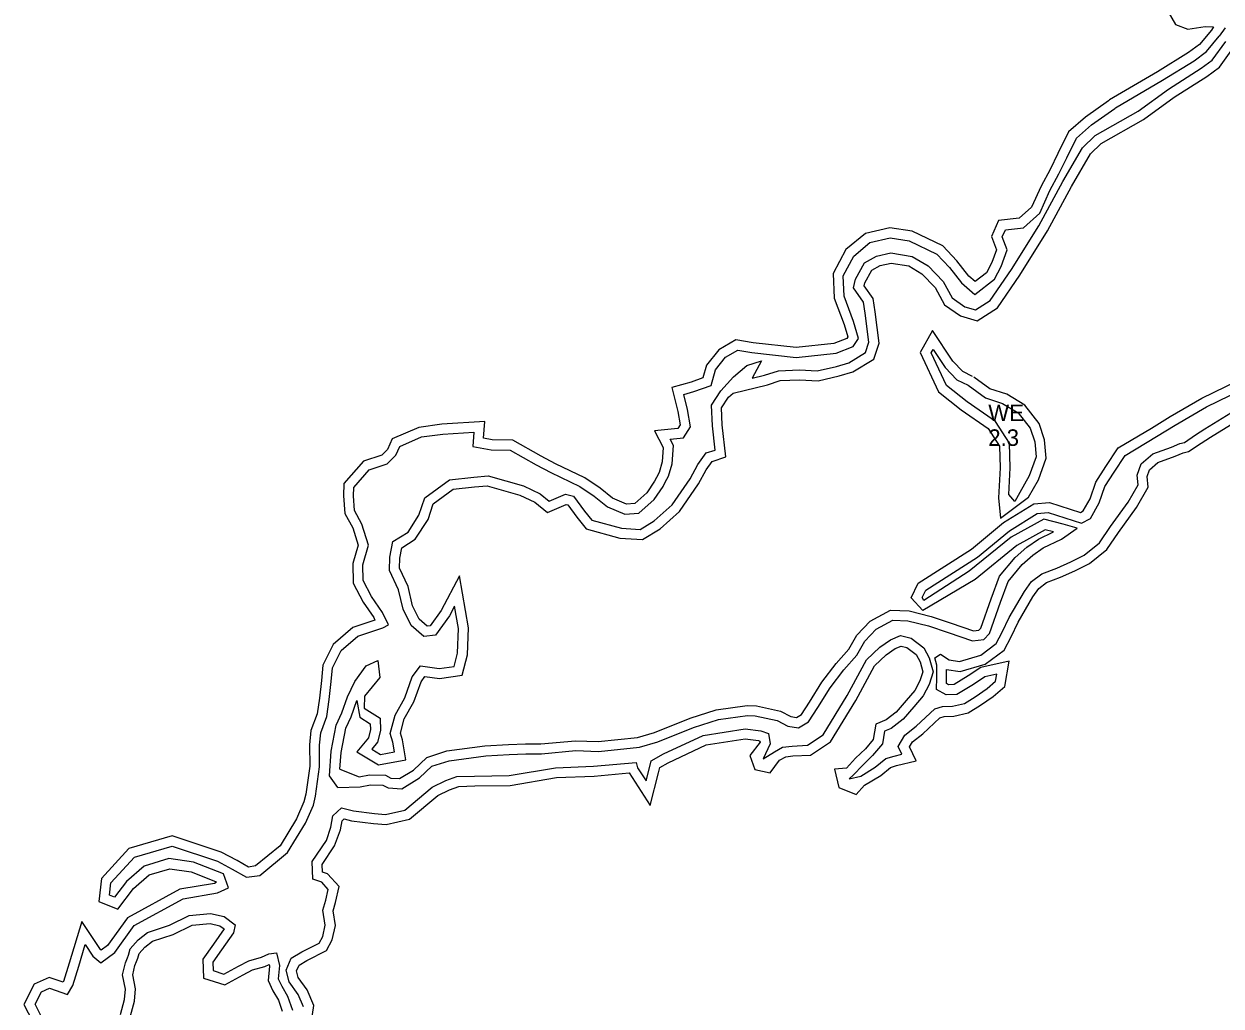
# Model space of a CAD drawing. Extents: x 2160437 to 2172832, y 205694 to 212444.
# Drawn here: x 2165066.3 to 2165428.5, y 210032.9 to 210329.8 of the extents above; entities that cross this region are included whole.
import ezdxf

# ---------------------------------------------------------------- set-up
doc = ezdxf.new("R2010")
doc.units = 0
for name, color, linetype in [('RD_EX_H2O', 7, 'Continuous'), ('RD_EX_H2O_Pond', 7, 'Continuous'), ('RD_EX_H2O_txCode', 7, 'Continuous'), ('RD_EX_VEG_ShrubLine', 7, 'Continuous')]:
    doc.layers.add(name, color=color, linetype=linetype)

msp = doc.modelspace()

# ---------------------------------------------------------------- linework, layer by layer
at = {"layer": 'RD_EX_H2O'}
for points in [[(2165429.66, 210328.63), (2165427.91, 210326.08)], [(2165072.34, 210028.17), (2165069.67, 210033.37), (2165071.61, 210037.18), (2165074.08, 210038.3), (2165079.52, 210036.37), (2165081.06, 210039.04), (2165082.9, 210044.94), (2165084.88, 210051.43), (2165087.17, 210047.96), (2165089.55, 210045.89), (2165093.77, 210049.05), (2165099.65, 210057.17), (2165114.45, 210065.29), (2165124.82, 210067.04), (2165128.16, 210068.62), (2165126.66, 210072.82), (2165117.64, 210076.4), (2165110.19, 210077.43), (2165102.71, 210075.17), (2165097.29, 210070.5), (2165093.7, 210065.8), (2165092.23, 210066.39), (2165092.62, 210070.11), (2165099.72, 210077.87), (2165111.14, 210081.2), (2165124.82, 210076.63), (2165129.32, 210074.22), (2165133.63, 210071.77), (2165137.67, 210072.37), (2165146.08, 210079.31), (2165151.48, 210088.12), (2165153.86, 210093.6), (2165154.52, 210096.3), (2165155.75, 210105.17), (2165155.71, 210111.71), (2165156.08, 210115.51), (2165157.96, 210120.43), (2165158.68, 210125.56), (2165159.29, 210130.98), (2165159.68, 210135.12), (2165162.29, 210140.32), (2165167.34, 210144.67), (2165174.87, 210147.21), (2165176.57, 210148.07), (2165174.75, 210151.81), (2165171.46, 210156.69), (2165168.94, 210161.52), (2165168.84, 210166.3), (2165170.57, 210172.24), (2165168.54, 210178.6), (2165166.34, 210182.69), (2165165.98, 210187.16), (2165166.06, 210189.65), (2165170.72, 210195.01), (2165176.2, 210196.83), (2165178.83, 210199.38), (2165180.01, 210202.04), (2165186.62, 210204.92), (2165193.01, 210205.8), (2165202.42, 210206.36), (2165202.08, 210202.08), (2165207.62, 210201.06), (2165213.39, 210200.96), (2165221.3, 210196.49), (2165225.72, 210194.17), (2165234.45, 210189.94), (2165238.81, 210187.05), (2165242.83, 210183.83), (2165248.06, 210181.57), (2165252.32, 210181.84), (2165257, 210186.05), (2165259.64, 210189.98), (2165260.32, 210191.24), (2165261.26, 210193.09), (2165262.39, 210196.85), (2165262.77, 210202.31), (2165261.78, 210204.25), (2165265.85, 210204.66), (2165267.98, 210207.97), (2165267.02, 210213.25), (2165265.93, 210217.81), (2165269.01, 210218.67), (2165274.19, 210220.5), (2165275.52, 210225.25), (2165278.51, 210229.01), (2165282.23, 210231.2), (2165286.51, 210230.44), (2165299.93, 210228.93), (2165312.01, 210230.22), (2165317.21, 210232.23), (2165318.79, 210234.7), (2165317.3, 210239.86), (2165314.4, 210247.5), (2165314.13, 210253.67), (2165317.32, 210259.63), (2165322.23, 210263.68), (2165328.39, 210265.15), (2165334.12, 210264.28), (2165342.45, 210260.23), (2165346.29, 210256.19), (2165349.97, 210251.5), (2165353.96, 210248.05), (2165359.88, 210252.62), (2165361.9, 210256.52), (2165363.71, 210261.53), (2165362.25, 210265.41), (2165363.21, 210267.56), (2165368.7, 210268.19), (2165373.64, 210272.58), (2165376.69, 210279.45), (2165379.4, 210284.48), (2165381.75, 210289.37), (2165384.68, 210295.32), (2165389.31, 210299.26), (2165396.31, 210304.24), (2165396.52, 210304.45), (2165410.78, 210312.81), (2165420.34, 210318.7), (2165424.02, 210321.44), (2165427.91, 210326.08)], [(2165161.3, 210098.98), (2165158.71, 210102.47), (2165159.28, 210109.95), (2165160.78, 210117.79), (2165162.52, 210121.46), (2165164.21, 210126.34), (2165166.44, 210130.98), (2165169.83, 210135.77), (2165173.41, 210137.36), (2165173.99, 210132.19), (2165169.35, 210126.58), (2165169.27, 210122.9), (2165174.05, 210119.88), (2165174.15, 210116.18), (2165173.28, 210112.61), (2165171.56, 210110.5), (2165174.16, 210108.92), (2165178.39, 210109.68), (2165177.91, 210112.65), (2165177.06, 210115.31), (2165178.59, 210120.8), (2165181.51, 210126.04), (2165183.77, 210132.35), (2165186.27, 210135.68), (2165191.97, 210134.89), (2165196.45, 210135.53), (2165197.49, 210139.51), (2165197.78, 210147.05), (2165196.61, 210153.74), (2165195.08, 210150.82), (2165190.81, 210144.99), (2165187.3, 210144.63), (2165183.44, 210147.96), (2165181.01, 210152.87), (2165179.66, 210158.75), (2165176.91, 210164.58), (2165177.02, 210168.6), (2165177.9, 210173.31), (2165182.53, 210176.17), (2165185.82, 210181.3), (2165187.54, 210186.53), (2165195.06, 210192), (2165202.36, 210192.78), (2165206.71, 210193.13), (2165217.39, 210190.19), (2165222.48, 210187.75), (2165225.16, 210185.55), (2165230.1, 210187.62), (2165232.6, 210187.05), (2165235.9, 210182.47), (2165238.11, 210179.75), (2165247.05, 210177.34), (2165252.71, 210176.99), (2165256.96, 210179.54), (2165262.4, 210184.38), (2165267.82, 210192.28), (2165270.15, 210196.58), (2165272.66, 210200.08), (2165275.39, 210200.97), (2165274.58, 210208.34), (2165274.34, 210214.56), (2165277.09, 210218.85), (2165280.99, 210223.06), (2165284.98, 210226.5), (2165289.4, 210227.96), (2165286.63, 210222.66), (2165290.39, 210223.57), (2165294.54, 210224.96), (2165300.95, 210225.23), (2165306.31, 210224.89), (2165312.14, 210226.26), (2165315.81, 210227.39), (2165320.87, 210230.42), (2165321.93, 210233.61), (2165320.84, 210242.36), (2165320.31, 210245.65), (2165317.29, 210250.05), (2165317.91, 210252.65), (2165320.64, 210257.61), (2165324.21, 210259.57), (2165328.55, 210260.58), (2165335.03, 210259.5), (2165339.82, 210256.66), (2165344.38, 210251.94), (2165347.09, 210246.96), (2165350.99, 210244.27), (2165354.22, 210243.32), (2165358.65, 210246.15), (2165365.09, 210255.52), (2165373.35, 210268.76), (2165380.6, 210282.14), (2165386.53, 210292.4), (2165390.41, 210296.13), (2165403.41, 210303.43), (2165412.54, 210310.11), (2165422.41, 210316.4), (2165425.8, 210318.91), (2165429.89, 210324.54)], [(2165161.3, 210098.98), (2165168.04, 210099.17), (2165171.13, 210099.78), (2165174.91, 210099.66), (2165176.52, 210098.83), (2165180.65, 210098.55), (2165185.99, 210101.82), (2165189.73, 210105.38), (2165194.9, 210107.04), (2165205.99, 210108.53), (2165213.06, 210108.93), (2165218.11, 210109.09), (2165222.84, 210109.09), (2165233.29, 210110.09), (2165240.12, 210109.82), (2165252.5, 210111.1), (2165258.06, 210112.71), (2165268.85, 210117.03), (2165276.41, 210119.49), (2165285.21, 210120.68), (2165287.52, 210120.62), (2165294.14, 210119.18), (2165297.4, 210117.5), (2165300.66, 210117.01), (2165303.67, 210118.79), (2165306.49, 210123.12), (2165310.21, 210129.08), (2165314.3, 210134.51), (2165318.31, 210138.97), (2165320.74, 210143.23), (2165324.13, 210146.81), (2165329.16, 210149.5), (2165333.65, 210149.36), (2165339.95, 210147.77), (2165345.86, 210145.81), (2165353.29, 210143.24), (2165356.65, 210143.66), (2165358.43, 210145.51), (2165361.74, 210155.01), (2165364.1, 210161.27), (2165368.33, 210166.35), (2165371.51, 210169.19), (2165374.69, 210171.38), (2165380.19, 210174.03), (2165384.91, 210177.39), (2165380.74, 210178.52), (2165374.88, 210180.04), (2165365, 210174.66), (2165352.26, 210164.3), (2165338.57, 210155.46), (2165338.08, 210156.39), (2165339.13, 210158.62), (2165354.74, 210168.54), (2165364.42, 210176.59), (2165372.79, 210181.81), (2165376.19, 210182.04), (2165386.24, 210178.9), (2165388.95, 210180.28), (2165391.6, 210185.03), (2165393.29, 210189.92), (2165396.08, 210194.32), (2165399.45, 210199.35), (2165408.97, 210205.02), (2165414.6, 210208.52), (2165424.06, 210214.03), (2165438.35, 210221)], [(2165150.89, 210032.59), (2165149.31, 210036.31), (2165146.54, 210040.21), (2165145.62, 210043.67), (2165147.14, 210047.31), (2165150.41, 210049.28), (2165155.64, 210051.88), (2165156.68, 210053.9), (2165157.48, 210057.32), (2165156.77, 210061.86), (2165157.62, 210064.87), (2165158.35, 210068.14), (2165156.39, 210070.27), (2165153.68, 210071.26), (2165153.49, 210076.56), (2165157.82, 210082.94), (2165159.19, 210086.92), (2165159.75, 210090.41), (2165162.38, 210092.75), (2165165.96, 210091.85), (2165172.4, 210091.03), (2165175.7, 210090.77), (2165181.56, 210092.1), (2165189.84, 210099), (2165193.9, 210101.01), (2165197.3, 210102.25), (2165202.61, 210102.39), (2165213.11, 210102.56), (2165227.1, 210104.92), (2165238.6, 210105.37), (2165251.48, 210106.52), (2165251.95, 210104.93), (2165254.56, 210100.9), (2165255.39, 210104.12), (2165256.05, 210106.95), (2165259.82, 210109.11), (2165271.8, 210114.7), (2165284.47, 210116.64), (2165289.18, 210116.05), (2165291.59, 210115.28), (2165292.1, 210112.15), (2165289.95, 210107.65), (2165293.33, 210109.74), (2165295.82, 210111.09), (2165298.66, 210111.48), (2165303.31, 210111.7), (2165308.12, 210114.9), (2165315.33, 210126.77), (2165321.23, 210137.52), (2165325.23, 210141.38), (2165328.41, 210143.57), (2165331.44, 210144.86), (2165334.68, 210144.05), (2165338.53, 210141.12), (2165340.2, 210138.13), (2165341.37, 210133.86), (2165340.13, 210130.07), (2165338.33, 210126.61), (2165335.47, 210123.33), (2165332.27, 210119.56), (2165328.64, 210116.79), (2165326.69, 210115.98), (2165326.05, 210112.16), (2165323.04, 210108.61), (2165320.05, 210105.72), (2165317.18, 210102.64), (2165315.94, 210101.6), (2165319.48, 210102.4), (2165323.83, 210105.06), (2165327.03, 210107.68), (2165329.52, 210108.44), (2165331.87, 210109.01), (2165330.76, 210111.3), (2165332.8, 210114.8), (2165336.25, 210117.47), (2165341.83, 210122.67), (2165344.14, 210123.44), (2165347.18, 210123.53), (2165350.82, 210124.37), (2165354.05, 210126.32), (2165357.73, 210128.86), (2165360.25, 210131.04), (2165360.62, 210133.21), (2165357.02, 210132.41), (2165353.55, 210130.11), (2165348.55, 210127.08), (2165345.3, 210127), (2165342.42, 210128.54), (2165342.44, 210132.22), (2165342.44, 210135.94), (2165341.9, 210138.18), (2165343.54, 210139.23), (2165346.22, 210137.5), (2165349.31, 210137.05), (2165355.74, 210138.91), (2165360.47, 210142.48), (2165362.24, 210145.86), (2165364.37, 210150.33), (2165368.97, 210158.21), (2165371.14, 210161.27), (2165374.21, 210163.53), (2165378.73, 210165.27), (2165382.97, 210167.14), (2165387, 210169.19), (2165391.64, 210172.91), (2165394.98, 210177.81), (2165400.39, 210185.21), (2165403.34, 210190.43), (2165403.05, 210193.35), (2165404.26, 210196.77), (2165407.77, 210199.82), (2165413.44, 210201.86), (2165416, 210202.98), (2165417.38, 210203.3), (2165420.74, 210205.55), (2165423.57, 210207.41), (2165434, 210213.82)], [(2165095.55, 210030.31), (2165096.74, 210034.81), (2165097.01, 210037.93), (2165096.16, 210042.29), (2165097.01, 210045.96), (2165097.59, 210047.47), (2165097.93, 210048.25), (2165098.41, 210050.2), (2165100.82, 210052.87), (2165103.73, 210055.11), (2165110.36, 210057.27), (2165116.34, 210060.22), (2165122.79, 210060.84), (2165126.85, 210059.94), (2165130.18, 210057.38), (2165129.71, 210054.98), (2165126.08, 210049.88), (2165123.44, 210046.1), (2165123.54, 210043.55), (2165126.77, 210042.53), (2165131.19, 210044.92), (2165134.37, 210046.56), (2165138.17, 210047.63), (2165140.35, 210048.62), (2165142.73, 210048.91), (2165143.65, 210045.11), (2165143.22, 210041.11), (2165144.31, 210038.89), (2165146.04, 210035.84), (2165147.51, 210031.6)]]:
    msp.add_lwpolyline(points, dxfattribs=at)
at = {"layer": 'RD_EX_H2O_Pond'}
msp.add_lwpolyline([(2165351.91, 210220.56), (2165357.16, 210216.74), (2165362.37, 210215.09), (2165367.11, 210212.27), (2165370.71, 210207.55), (2165372.08, 210203.47), (2165372.51, 210198.91), (2165370.44, 210193.17), (2165367.63, 210188.18), (2165366.1, 210185.39), (2165364.23, 210187.53), (2165364.67, 210195.55), (2165364.42, 210203.09), (2165360.22, 210209.57), (2165351.6, 210215.55), (2165345.39, 210220.46), (2165340.79, 210230.35), (2165341.36, 210231.36), (2165344.99, 210225.91), (2165348.57, 210222.23)], close=True, dxfattribs=at)
at = {"layer": 'RD_EX_VEG_ShrubLine'}
for points in [[(2165411.32, 210335.42), (2165414.65, 210329.69), (2165418.36, 210328.2), (2165418.36, 210328.2), (2165423.68, 210329.01), (2165426.2, 210328.89), (2165425.52, 210327.9), (2165421.94, 210323.64), (2165418.65, 210321.18), (2165409.23, 210315.38), (2165394.69, 210306.85), (2165394.38, 210306.55), (2165387.46, 210301.63), (2165382.27, 210297.2), (2165379.05, 210290.68), (2165376.72, 210285.84), (2165373.99, 210280.77), (2165371.16, 210274.4), (2165367.41, 210271.06), (2165361.16, 210270.35), (2165359.01, 210265.51), (2165360.51, 210261.51), (2165359.15, 210257.72), (2165357.52, 210254.59), (2165354.06, 210251.93), (2165352.15, 210253.58), (2165348.57, 210258.15), (2165344.25, 210262.69), (2165335.02, 210267.18), (2165328.27, 210268.2), (2165320.86, 210266.44), (2165314.95, 210261.57), (2165311.1, 210254.36), (2165311.42, 210246.89), (2165314.45, 210238.91), (2165315.53, 210235.17), (2165315.21, 210234.67), (2165311.29, 210233.16), (2165299.93, 210231.94), (2165286.94, 210233.41), (2165281.67, 210234.34), (2165276.51, 210231.32), (2165272.79, 210226.64), (2165271.73, 210222.81), (2165268.11, 210221.53), (2165262.34, 210219.93), (2165264.09, 210212.63), (2165264.82, 210208.6), (2165264.11, 210207.5), (2165257.09, 210206.8), (2165259.72, 210201.69), (2165259.42, 210197.39), (2165258.47, 210194.21), (2165257.66, 210192.63), (2165257.07, 210191.53), (2165254.72, 210188.04), (2165251.09, 210184.77), (2165248.59, 210184.61), (2165244.39, 210186.42), (2165240.58, 210189.48), (2165235.94, 210192.55), (2165227.07, 210196.85), (2165222.73, 210199.13), (2165214.2, 210203.95), (2165207.92, 210204.05), (2165205.29, 210204.54), (2165205.69, 210209.56), (2165192.71, 210208.79), (2165185.8, 210207.83), (2165177.74, 210204.32), (2165176.33, 210201.13), (2165174.61, 210199.47), (2165168.99, 210197.6), (2165163.1, 210190.81), (2165162.98, 210187.09), (2165163.4, 210181.83), (2165165.76, 210177.42), (2165167.44, 210172.2), (2165165.83, 210166.7), (2165165.95, 210160.76), (2165168.98, 210155.01), (2165168.98, 210155.01), (2165172.15, 210150.31), (2165172.51, 210149.57), (2165165.82, 210147.33), (2165159.87, 210142.2), (2165156.75, 210135.97), (2165156.3, 210131.29), (2165155.7, 210125.93), (2165155.04, 210121.18), (2165153.13, 210116.2), (2165152.71, 210111.85), (2165152.75, 210105.36), (2165151.56, 210096.87), (2165151, 210094.56), (2165148.81, 210089.5), (2165143.78, 210081.3), (2165136.4, 210075.21), (2165134.21, 210074.89), (2165130.77, 210076.84), (2165126.01, 210079.4), (2165111.2, 210084.34), (2165098.07, 210080.52), (2165089.74, 210071.41), (2165089.01, 210064.46), (2165094.7, 210062.16), (2165099.48, 210068.43), (2165104.19, 210072.48), (2165110.43, 210074.36), (2165116.87, 210073.48), (2165124.29, 210070.53), (2165124.42, 210070.17), (2165123.91, 210069.93), (2165113.45, 210068.16), (2165097.61, 210059.48), (2165091.6, 210051.18), (2165089.69, 210049.74), (2165089.45, 210049.95), (2165083.87, 210058.41), (2165080.03, 210045.82), (2165078.29, 210040.25), (2165078.17, 210040.03), (2165073.94, 210041.53), (2165069.41, 210039.48), (2165066.31, 210033.36), (2165070.19, 210025.79)], [(2165161.87, 210104.45), (2165162.25, 210109.55), (2165163.65, 210116.85), (2165165.3, 210120.32), (2165166.98, 210125.2), (2165167.95, 210120.19), (2165171.09, 210118.2), (2165171.14, 210116.5), (2165170.52, 210113.98), (2165167.06, 210109.71), (2165173.58, 210105.77), (2165181.83, 210107.25), (2165180.84, 210113.36), (2165180.19, 210115.37), (2165181.38, 210119.65), (2165184.25, 210124.79), (2165186.44, 210130.91), (2165187.61, 210132.46), (2165191.98, 210131.86), (2165198.85, 210132.85), (2165200.48, 210139.06), (2165200.79, 210147.25), (2165198.06, 210162.93), (2165192.53, 210152.42), (2165189.18, 210147.84), (2165188.28, 210147.74), (2165185.86, 210149.83), (2165183.85, 210153.89), (2165182.51, 210159.73), (2165179.93, 210165.21), (2165180.01, 210168.28), (2165180.61, 210171.45), (2165184.69, 210173.98), (2165188.55, 210180), (2165190.09, 210184.67), (2165196.18, 210189.11), (2165202.64, 210189.8), (2165206.42, 210190.1), (2165216.34, 210187.37), (2165220.86, 210185.21), (2165224.65, 210182.08), (2165230.37, 210184.48), (2165230.83, 210184.37), (2165233.52, 210180.64), (2165236.4, 210177.1), (2165246.56, 210174.36), (2165253.45, 210173.94), (2165258.74, 210177.11), (2165264.67, 210182.38), (2165270.38, 210190.71), (2165272.7, 210194.99), (2165274.52, 210197.53), (2165278.64, 210198.87), (2165277.58, 210208.56), (2165277.38, 210213.74), (2165279.47, 210217.01), (2165280.91, 210218.19), (2165291.22, 210220.68), (2165295.09, 210221.98), (2165300.92, 210222.23), (2165306.57, 210221.87), (2165312.92, 210223.37), (2165317.04, 210224.63), (2165323.37, 210228.42), (2165324.99, 210233.31), (2165323.81, 210242.78), (2165323.17, 210246.79), (2165320.52, 210250.65), (2165320.73, 210251.56), (2165322.85, 210255.4), (2165325.29, 210256.74), (2165328.65, 210257.52), (2165333.98, 210256.64), (2165337.94, 210254.28), (2165341.94, 210250.15), (2165344.79, 210244.9), (2165349.68, 210241.53), (2165354.68, 210240.06), (2165360.78, 210243.95), (2165367.6, 210253.88), (2165375.94, 210267.25), (2165383.22, 210280.68), (2165388.92, 210290.53), (2165392.21, 210293.71), (2165405.04, 210300.9), (2165414.24, 210307.63), (2165424.11, 210313.93), (2165427.95, 210316.78), (2165432.53, 210323.12)], [(2165353.25, 210223.25), (2165350.37, 210224.68), (2165347.33, 210227.8), (2165341.14, 210237.09), (2165337.42, 210230.48), (2165342.97, 210218.55), (2165349.82, 210213.14), (2165358.02, 210207.44), (2165361.45, 210202.16), (2165361.67, 210195.58), (2165361.17, 210186.48), (2165361.72, 210180.39), (2165370.25, 210186.72), (2165373.18, 210191.92), (2165375.56, 210198.52), (2165375.03, 210204.1), (2165373.4, 210208.98), (2165369.14, 210214.55), (2165363.6, 210217.84), (2165358.54, 210219.45), (2165353.68, 210222.99)], [(2165161.87, 210104.45), (2165167.71, 210102.16), (2165170.88, 210102.79), (2165175.68, 210102.64), (2165177.34, 210101.78), (2165179.9, 210101.61), (2165184.16, 210104.21), (2165188.16, 210108.02), (2165194.23, 210109.98), (2165205.71, 210111.52), (2165212.93, 210111.93), (2165218.06, 210112.09), (2165222.7, 210112.09), (2165233.21, 210113.09), (2165240.02, 210112.82), (2165251.92, 210114.06), (2165257.09, 210115.55), (2165267.83, 210119.85), (2165275.74, 210122.43), (2165285.05, 210123.69), (2165287.89, 210123.61), (2165295.16, 210122.03), (2165298.34, 210120.39), (2165300.05, 210120.13), (2165301.54, 210121.01), (2165303.96, 210124.73), (2165307.73, 210130.77), (2165311.98, 210136.42), (2165315.87, 210140.73), (2165318.31, 210145.02), (2165322.28, 210149.23), (2165328.45, 210152.52), (2165334.07, 210152.35), (2165340.8, 210150.65), (2165346.82, 210148.65), (2165353.61, 210146.3), (2165355.22, 210146.5), (2165355.81, 210147.12), (2165358.92, 210156.03), (2165361.47, 210162.8), (2165366.17, 210168.44), (2165369.65, 210171.56), (2165373.19, 210173.98), (2165377.77, 210176.2), (2165375.28, 210176.84), (2165366.68, 210172.15), (2165354.03, 210161.87), (2165338.21, 210152.49), (2165334.74, 210156.32), (2165336.79, 210160.69), (2165352.97, 210170.97), (2165362.66, 210179.03), (2165371.84, 210184.75), (2165376.55, 210185.07), (2165385.97, 210182.13), (2165386.77, 210182.54), (2165388.85, 210186.26), (2165390.56, 210191.23), (2165393.56, 210195.96), (2165397.33, 210201.59), (2165407.41, 210207.58), (2165413.05, 210211.09), (2165422.64, 210216.68), (2165437.16, 210223.75)], [(2165152.72, 210024.17), (2165153.98, 210032.99), (2165151.94, 210037.79), (2165149.3, 210041.5), (2165148.78, 210043.46), (2165149.53, 210045.25), (2165151.85, 210046.65), (2165157.85, 210049.63), (2165159.52, 210052.85), (2165160.54, 210057.21), (2165159.83, 210061.68), (2165160.53, 210064.13), (2165161.63, 210069.02), (2165158.1, 210072.83), (2165156.61, 210073.38), (2165156.52, 210075.69), (2165160.3, 210081.26), (2165160.3, 210081.26), (2165162.11, 210086.18), (2165162.54, 210088.88), (2165163.19, 210089.46), (2165165.41, 210088.9), (2165172.09, 210088.05), (2165175.92, 210087.74), (2165182.93, 210089.33), (2165191.49, 210096.47), (2165195.09, 210098.25), (2165197.87, 210099.27), (2165202.67, 210099.39), (2165213.39, 210099.56), (2165227.41, 210101.93), (2165238.79, 210102.37), (2165249.42, 210103.32), (2165255.76, 210093.53), (2165258.31, 210103.41), (2165258.68, 210105), (2165261.21, 210106.44), (2165272.68, 210111.8), (2165284.51, 210113.61), (2165288.53, 210113.11), (2165288.92, 210112.98), (2165288.98, 210112.6), (2165285.93, 210108.56), (2165287.41, 210104.42), (2165292.07, 210103.35), (2165294.84, 210107.15), (2165296.77, 210108.2), (2165298.94, 210108.49), (2165304.28, 210108.74), (2165310.34, 210112.77), (2165317.93, 210125.27), (2165323.65, 210135.68), (2165327.13, 210139.05), (2165329.86, 210140.92), (2165331.69, 210141.71), (2165333.35, 210141.29), (2165336.22, 210139.11), (2165337.41, 210136.98), (2165338.24, 210133.94), (2165337.36, 210131.23), (2165335.84, 210128.31), (2165333.19, 210125.28), (2165330.19, 210121.75), (2165327.13, 210119.41), (2165324.01, 210118.11), (2165323.23, 210113.47), (2165320.85, 210110.67), (2165317.9, 210107.82), (2165315.12, 210104.82), (2165311.49, 210104.52), (2165312.83, 210098.95), (2165318.02, 210096.81), (2165320.62, 210099.59), (2165325.57, 210102.6), (2165328.47, 210104.98), (2165330.31, 210105.54), (2165336.19, 210106.98), (2165334.16, 210111.18), (2165335.09, 210112.79), (2165338.2, 210115.18), (2165343.39, 210120.02), (2165344.67, 210120.45), (2165347.57, 210120.54), (2165351.96, 210121.55), (2165355.68, 210123.8), (2165359.56, 210126.48), (2165363.03, 210129.47), (2165364.31, 210137.11), (2165355.83, 210135.21), (2165351.94, 210132.65), (2165347.67, 210130.06), (2165346.02, 210130.02), (2165345.43, 210130.33), (2165345.44, 210132.22), (2165345.44, 210134.58), (2165349.53, 210133.99), (2165357.1, 210136.18), (2165362.81, 210140.49), (2165364.92, 210144.51), (2165367.03, 210148.93), (2165371.5, 210156.58), (2165373.31, 210159.14), (2165375.67, 210160.88), (2165379.87, 210162.5), (2165384.26, 210164.42), (2165388.63, 210166.65), (2165393.87, 210170.85), (2165397.44, 210176.08), (2165402.92, 210183.58), (2165406.42, 210189.79), (2165406.1, 210192.98), (2165406.83, 210195.02), (2165409.32, 210197.19), (2165414.55, 210199.07), (2165416.95, 210200.12), (2165418.59, 210200.5), (2165422.4, 210203.05), (2165425.22, 210204.9), (2165425.22, 210204.9), (2165435.24, 210211.06)], [(2165098.55, 210029.93), (2165099.71, 210034.3), (2165100.04, 210038.09), (2165099.23, 210042.24), (2165099.89, 210045.08), (2165100.36, 210046.33), (2165100.79, 210047.28), (2165101.14, 210048.75), (2165102.87, 210050.66), (2165105.16, 210052.42), (2165111.49, 210054.49), (2165117.17, 210057.29), (2165122.6, 210057.81), (2165125.55, 210057.15), (2165126.86, 210056.15), (2165123.63, 210051.61), (2165120.41, 210047), (2165120.62, 210041.32), (2165127.08, 210039.29), (2165132.59, 210042.27), (2165135.48, 210043.76), (2165139.2, 210044.81), (2165140.49, 210045.39), (2165140.61, 210044.91), (2165140.15, 210040.57), (2165141.65, 210037.49), (2165143.3, 210034.6), (2165144.43, 210031.33)]]:
    msp.add_lwpolyline(points, dxfattribs=at)

# ---------------------------------------------------------------- texts
at = {"layer": 'RD_EX_H2O_txCode'}
for s, p in [('WE', (2165358.04, 210209.73)), ('2.3', (2165358.04, 210202.23))]:
    msp.add_text(s, height=5, dxfattribs=at).set_placement(p)

doc.saveas('drawing.dxf')
